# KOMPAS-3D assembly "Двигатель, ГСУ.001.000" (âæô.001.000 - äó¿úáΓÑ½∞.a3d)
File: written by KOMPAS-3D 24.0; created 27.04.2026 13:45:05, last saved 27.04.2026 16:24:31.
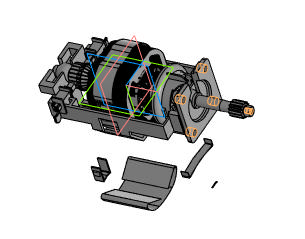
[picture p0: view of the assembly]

Document properties: Автор: User7; Полное имя файла: ГСУ.001.000 - Двигатель.cdw

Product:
- Component [detail]: Рама двигателя  | designation ГСУ.001.001  | qty 1  | pos. 4  | Масса: 0.221971; Автор: User7; source file: ГСУ.001.001 - Рама двигателя.m3d
- Component [assembly]: Ротор  | designation ГСУ.001.100  | qty 1  | pos. 1  | Масса: 0.279522; source file: ГСУ.001.100 - Ротор.a3d
- Component [detail]: Обмотка  | designation ГСУ.001.009  | qty 2  | pos. 12  | Масса: 0.009726; Автор: User7; source file: ГСУ.001.009 - Обмотка.m3d
- Component [detail]: Держатель статора  | designation ГСУ.001.012  | qty 2  | pos. 15  | Масса: 0.004314; Автор: User7; source file: ГСУ.001.012 - Держатель статора.m3d
- Component [detail]: Пластина держателя пружин  | designation ГСУ.001.011  | qty 1  | pos. 14  | Масса: 0.000005; Автор: User7; source file: ГСУ.001.011 - Пластина держателя пружин.m3d
- Component [detail]: Пластина держателя втулок ротора  | designation ГСУ.001.013  | qty 1  | pos. 16  | Масса: 0.000957; Автор: User7; source file: ГСУ.001.013 - Пластина держателя втулок ротора.m3d
- Component [detail]: Уплотнитель  | designation ГСУ.001.007  | qty 1  | pos. 10  | Масса: 0.011541; Автор: User7; source file: ГСУ.001.007 - Уплотнитель.m3d
- Component [detail]: Основание статора  | designation ГСУ.001.002  | qty 1  | pos. 5  | Масса: 0.01025; Автор: User7; source file: ГСУ.001.002 - Основание статора.m3d
- Component [detail]: Держатель щеток  | designation ГСУ.001.003  | qty 2  | pos. 6  | Масса: 0.006051; Автор: User7; source file: ГСУ.001.003 - Держатель щеток.m3d
- Component [detail]: Щетка  | designation ГСУ.001.004  | qty 2  | pos. 7  | Масса: 0.001131; Автор: User7; source file: ГСУ.001.004 - Щетка.m3d
- Component [detail]: Пластина  | designation ГСУ.001.005  | qty 1  | pos. 8  | Масса: 0.002726; Автор: User7; source file: ГСУ.001.005 - Пластина.m3d
- Component [detail]: Пластинка  | designation ГСУ.001.006  | qty 1  | pos. 9  | Масса: 0.001875; Автор: User7; source file: ГСУ.001.006 - Пластинка.m3d
- Component [detail]: Пружина  | designation ГСУ.001.008  | qty 2  | pos. 11  | Масса: 0.00001; Автор: User7; source file: ГСУ.001.008 - Пружина.m3d
- Component [detail]: Резистор  | designation ГСУ.001.010  | qty 2  | pos. 13  | Масса: 0.000476; Автор: User7; source file: ГСУ.001.010 - Резистор.m3d
- Part/product: Двигатель  | designation ГСУ.001.000
    Масса: 0.572265
    Форматы листов документа: A4
    source file: ГСУ.001.000 - Двигатель.spw

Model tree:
1. Массив по концентрической сетке:1  (with: Грань.Элемент выдавливания:1)  (2 pattern instances)
     Шаг 2 = 360
2. Средняя плоскость:1  (with: Грань.Элемент выдавливания:5)
3. Ось на пересечении двух плоскостей:1
4. Массив по концентрической сетке:2  (with: Грань.Элемент вращения:1, Грань.Элемент выдавливания:6, Грань.Элемент выдавливания:2, Грань.Элемент выдавливания:5, Грань.Элемент выдавливания:3, Грань.Элемент выдавливания:1)  (labels: Грань.Элемент выдавливания:1.Экземпляр ( 2 ))  (2 pattern instances)
     Шаг 2 = 360; Расстояние = 2

Referenced files in C:\Users\User7\Desktop\ГМ_27_04_337-02\: ГСУ.001.001 - Рама двигателя.m3d, ГСУ.001.100 - Ротор.a3d, ГСУ.001.009 - Обмотка.m3d, ГСУ.001.012 - Держатель статора.m3d, ГСУ.001.011 - Пластина держателя пружин.m3d, ГСУ.001.013 - Пластина держателя втулок ротора.m3d, ГСУ.001.007 - Уплотнитель.m3d, ГСУ.001.002 - Основание статора.m3d, ГСУ.001.003 - Держатель щеток.m3d, ГСУ.001.004 - Щетка.m3d, ГСУ.001.005 - Пластина.m3d, ГСУ.001.006 - Пластинка.m3d, ГСУ.001.008 - Пружина.m3d, ГСУ.001.010 - Резистор.m3d
Referenced files in C:\Users\User7\Desktop\олимп\: ГСУ.001.012 - Держатель статора.m3d, ГСУ.001.009 - Обмотка.m3d, ГСУ.001.010 - Резистор.m3d, ГСУ.001.003 - Держатель щеток.m3d, ГСУ.001.008 - Пружина.m3d, ГСУ.001.004 - Щетка.m3d
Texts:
  ГСУ.001.000
  ГСУ.001.001 Рама двигателя
  ГСУ.001.100 Ротор
  ГСУ.001.009 Обмотка (1)
  ГСУ.001.012 Держатель статора (1)
  ГСУ.001.011 Пластина держателя пружин
  ГСУ.001.013 Пластина держателя втулок ротора
  ГСУ.001.007 Уплотнитель
  ГСУ.001.002 Основание статора
  ГСУ.001.003 Держатель щеток (1)
  ГСУ.001.004 Щетка (1)
  ГСУ.001.005 Пластина
  ГСУ.001.006 Пластинка
  ГСУ.001.008 Пружина (1)
  ГСУ.001.010 Резистор (1)
  ГСУ.001.012 Держатель статора (2)
  ГСУ.001.009 Обмотка (2)
  ГСУ.001.010 Резистор (2)
  ГСУ.001.003 Держатель щеток (2)
  ГСУ.001.008 Пружина (2)
  ГСУ.001.004 Щетка (2)
  Плоскость ZY.Начало координат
